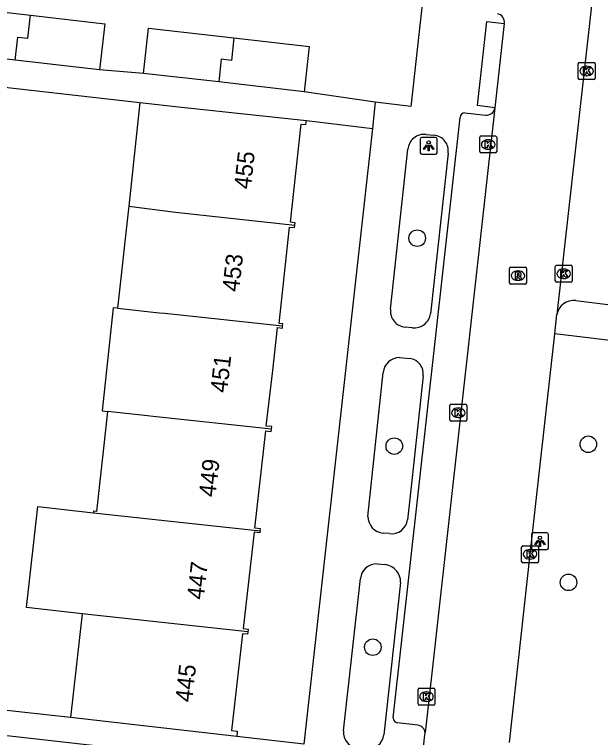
# Model space of a CAD drawing. Extents: x 161928 to 163055, y 386475 to 387428.
# Drawn here: x 162068.43 to 162103.08, y 386978.31 to 387021.04 of the extents above; entities that cross this region are included whole.
import ezdxf

# ---------------------------------------------------------------- set-up
doc = ezdxf.new("R2010")
doc.units = 0
for name, color, linetype in [('IMGEO_Boom', 7, 'Continuous'), ('IMGEO_Kolk', 7, 'Continuous'), ('IMGEO_Lichtpunt', 7, 'Continuous'), ('IMGEO_Pand', 7, 'Continuous'), ('IMGEO_Pand_nummerreeks', 7, 'Continuous'), ('IMGEO_Rijbaan_lokaal_open', 7, 'Continuous'), ('IMGEO_Rioolput', 7, 'Continuous'), ('IMGEO_Voetpad_gesloten', 7, 'Continuous'), ('IMGEO_Voetpad_open', 7, 'Continuous')]:
    doc.layers.add(name, color=color, linetype=linetype)

msp = doc.modelspace()

# ---------------------------------------------------------------- linework, layer by layer
at = {"layer": 'IMGEO_Boom'}
for centre in [(162092.243, 387007.82), (162090.886, 386995.528), (162102.36, 386995.64), (162101.189, 386987.475), (162089.615, 386983.644)]:
    msp.add_circle(centre, 0.489, dxfattribs=at)
at = {"layer": 'IMGEO_Kolk'}
for p, q in [((162101.762, 387017.272), (162101.762, 387018.124)), ((162101.837, 387018.198), (162102.689, 387018.198)), ((162102.763, 387018.124), (162102.763, 387017.272)), ((162102.25, 387017.978), (162102.275, 387017.978)), ((162102.689, 387017.198), (162101.837, 387017.198)), ((162102.273, 387017.418), (162102.248, 387017.418)), ((162095.94, 387012.932), (162095.94, 387013.784)), ((162096.015, 387013.858), (162096.867, 387013.858)), ((162096.941, 387013.784), (162096.941, 387012.932)), ((162096.428, 387013.638), (162096.453, 387013.638)), ((162096.451, 387013.078), (162096.426, 387013.078)), ((162096.867, 387012.858), (162096.015, 387012.858)), ((162100.407, 387005.289), (162100.407, 387006.141)), ((162100.482, 387006.215), (162101.334, 387006.215)), ((162101.408, 387006.141), (162101.408, 387005.289)), ((162100.895, 387005.995), (162100.92, 387005.995)), ((162101.334, 387005.215), (162100.482, 387005.215)), ((162100.918, 387005.435), (162100.893, 387005.435)), ((162094.169, 386997.074), (162094.169, 386997.926)), ((162094.244, 386998), (162095.096, 386998)), ((162095.17, 386997.926), (162095.17, 386997.074)), ((162094.657, 386997.78), (162094.682, 386997.78)), ((162094.68, 386997.22), (162094.655, 386997.22)), ((162095.096, 386997), (162094.244, 386997)), ((162098.417, 386988.711), (162098.417, 386989.563)), ((162098.492, 386989.637), (162099.344, 386989.637)), ((162098.905, 386989.417), (162098.93, 386989.417)), ((162099.418, 386989.563), (162099.418, 386988.711)), ((162099.344, 386988.637), (162098.492, 386988.637)), ((162098.928, 386988.857), (162098.903, 386988.857)), ((162092.289, 386980.297), (162092.289, 386981.149)), ((162092.364, 386981.223), (162093.216, 386981.223)), ((162092.777, 386981.003), (162092.802, 386981.003)), ((162093.29, 386981.149), (162093.29, 386980.297)), ((162092.8, 386980.443), (162092.775, 386980.443)), ((162093.216, 386980.223), (162092.364, 386980.223))]:
    msp.add_line(p, q, dxfattribs=at)
for points in [[(162101.762, 387017.272), (162101.762, 387018.124)], [(162101.837, 387018.198), (162102.689, 387018.198)], [(162102.763, 387018.124), (162102.763, 387017.272)], [(162102.083, 387017.898), (162102.206, 387017.898), (162102.206, 387017.747), (162102.336, 387017.898), (162102.5, 387017.898), (162102.354, 387017.747), (162102.507, 387017.498), (162102.355, 387017.498), (162102.27, 387017.662), (162102.206, 387017.595), (162102.206, 387017.498), (162102.083, 387017.498), (162102.083, 387017.898)], [(162102.689, 387017.198), (162101.837, 387017.198)], [(162095.94, 387012.932), (162095.94, 387013.784)], [(162096.015, 387013.858), (162096.867, 387013.858)], [(162096.941, 387013.784), (162096.941, 387012.932)], [(162096.261, 387013.558), (162096.384, 387013.558), (162096.384, 387013.407), (162096.514, 387013.558), (162096.678, 387013.558), (162096.532, 387013.407), (162096.685, 387013.158), (162096.533, 387013.158), (162096.448, 387013.322), (162096.384, 387013.255), (162096.384, 387013.158), (162096.261, 387013.158), (162096.261, 387013.558)], [(162096.867, 387012.858), (162096.015, 387012.858)], [(162100.407, 387005.289), (162100.407, 387006.141)], [(162100.482, 387006.215), (162101.334, 387006.215)], [(162101.408, 387006.141), (162101.408, 387005.289)], [(162100.728, 387005.915), (162100.851, 387005.915), (162100.851, 387005.764), (162100.981, 387005.915), (162101.145, 387005.915), (162100.999, 387005.764), (162101.152, 387005.515), (162101, 387005.515), (162100.915, 387005.679), (162100.851, 387005.612), (162100.851, 387005.515), (162100.728, 387005.515), (162100.728, 387005.915)], [(162101.334, 387005.215), (162100.482, 387005.215)], [(162094.169, 386997.074), (162094.169, 386997.926)], [(162094.244, 386998), (162095.096, 386998)], [(162095.17, 386997.926), (162095.17, 386997.074)], [(162094.49, 386997.7), (162094.613, 386997.7), (162094.613, 386997.549), (162094.743, 386997.7), (162094.907, 386997.7), (162094.761, 386997.549), (162094.914, 386997.3), (162094.762, 386997.3), (162094.677, 386997.464), (162094.613, 386997.397), (162094.613, 386997.3), (162094.49, 386997.3), (162094.49, 386997.7)], [(162095.096, 386997), (162094.244, 386997)], [(162098.417, 386988.711), (162098.417, 386989.563)], [(162098.492, 386989.637), (162099.344, 386989.637)], [(162099.418, 386989.563), (162099.418, 386988.711)], [(162098.738, 386989.337), (162098.861, 386989.337), (162098.861, 386989.186), (162098.991, 386989.337), (162099.155, 386989.337), (162099.009, 386989.186), (162099.162, 386988.937), (162099.01, 386988.937), (162098.925, 386989.101), (162098.861, 386989.034), (162098.861, 386988.937), (162098.738, 386988.937), (162098.738, 386989.337)], [(162099.344, 386988.637), (162098.492, 386988.637)], [(162092.289, 386980.297), (162092.289, 386981.149)], [(162092.364, 386981.223), (162093.216, 386981.223)], [(162092.61, 386980.923), (162092.733, 386980.923), (162092.733, 386980.772), (162092.863, 386980.923), (162093.027, 386980.923), (162092.881, 386980.772), (162093.034, 386980.523), (162092.882, 386980.523), (162092.797, 386980.687), (162092.733, 386980.62), (162092.733, 386980.523), (162092.61, 386980.523), (162092.61, 386980.923)], [(162093.29, 386981.149), (162093.29, 386980.297)], [(162093.216, 386980.223), (162092.364, 386980.223)]]:
    msp.add_lwpolyline(points, dxfattribs=at)
for centre, start, end in [((162101.839, 387018.122), 91.552, 178.448), ((162101.839, 387018.122), 91.552, 178.448), ((162102.687, 387018.122), 1.552, 88.448), ((162102.687, 387018.122), 1.552, 88.448), ((162101.839, 387017.274), 181.552, 268.448), ((162101.839, 387017.274), 181.552, 268.448), ((162102.687, 387017.274), 271.552, 358.448), ((162102.687, 387017.274), 271.552, 358.448), ((162096.017, 387013.782), 91.552, 178.448), ((162096.017, 387013.782), 91.552, 178.448), ((162096.865, 387013.782), 1.552, 88.448), ((162096.865, 387013.782), 1.552, 88.448), ((162096.017, 387012.934), 181.552, 268.448), ((162096.017, 387012.934), 181.552, 268.448), ((162096.865, 387012.934), 271.552, 358.448), ((162096.865, 387012.934), 271.552, 358.448), ((162100.484, 387006.139), 91.552, 178.448), ((162100.484, 387006.139), 91.552, 178.448), ((162101.332, 387006.139), 1.552, 88.448), ((162101.332, 387006.139), 1.552, 88.448), ((162100.484, 387005.291), 181.552, 268.448), ((162100.484, 387005.291), 181.552, 268.448), ((162101.332, 387005.291), 271.552, 358.448), ((162101.332, 387005.291), 271.552, 358.448), ((162094.246, 386997.924), 91.552, 178.448), ((162094.246, 386997.924), 91.552, 178.448), ((162095.094, 386997.924), 1.552, 88.448), ((162095.094, 386997.924), 1.552, 88.448), ((162094.246, 386997.076), 181.552, 268.448), ((162094.246, 386997.076), 181.552, 268.448), ((162095.094, 386997.076), 271.552, 358.448), ((162095.094, 386997.076), 271.552, 358.448), ((162098.494, 386989.561), 91.552, 178.448), ((162098.494, 386989.561), 91.552, 178.448), ((162099.342, 386989.561), 1.552, 88.448), ((162099.342, 386989.561), 1.552, 88.448), ((162098.494, 386988.713), 181.552, 268.448), ((162098.494, 386988.713), 181.552, 268.448), ((162099.342, 386988.713), 271.552, 358.448), ((162099.342, 386988.713), 271.552, 358.448), ((162092.366, 386981.147), 91.552, 178.448), ((162092.366, 386981.147), 91.552, 178.448), ((162093.214, 386981.147), 1.552, 88.448), ((162093.214, 386981.147), 1.552, 88.448), ((162092.366, 386980.299), 181.552, 268.448), ((162092.366, 386980.299), 181.552, 268.448), ((162093.214, 386980.299), 271.552, 358.448), ((162093.214, 386980.299), 271.552, 358.448)]:
    msp.add_arc(centre, 0.0765, start, end, dxfattribs=at)
for centre, major_axis, ratio, start_param, end_param in [((162102.249, 387017.698), (-0.387, 0.002), 0.722429, 4.712389, 7.853982), ((162102.274, 387017.698), (-0.39, 0.002), 0.717154, 1.570796, 4.712389), ((162096.427, 387013.358), (-0.387, 0.002), 0.722429, 4.712389, 7.853982), ((162096.452, 387013.358), (-0.39, 0.002), 0.717154, 1.570796, 4.712389), ((162100.894, 387005.715), (-0.387, 0.002), 0.722429, 4.712389, 7.853982), ((162100.919, 387005.715), (-0.39, 0.002), 0.717154, 1.570796, 4.712389), ((162094.656, 386997.5), (-0.387, 0.002), 0.722429, 4.712389, 7.853982), ((162094.681, 386997.5), (-0.39, 0.002), 0.717154, 1.570796, 4.712389), ((162098.904, 386989.137), (-0.387, 0.002), 0.722429, 4.712389, 7.853982), ((162098.929, 386989.137), (-0.39, 0.002), 0.717154, 1.570796, 4.712389), ((162092.776, 386980.723), (-0.387, 0.002), 0.722429, 4.712389, 7.853982), ((162092.801, 386980.723), (-0.39, 0.002), 0.717154, 1.570796, 4.712389)]:
    msp.add_ellipse(centre, major_axis=major_axis, ratio=ratio, start_param=start_param, end_param=end_param, dxfattribs=at)
at = {"layer": 'IMGEO_Lichtpunt'}
for p, q in [((162093.323, 387013.772), (162092.515, 387013.772)), ((162093.323, 387013.772), (162092.515, 387013.772)), ((162092.421, 387013.677), (162092.421, 387012.87)), ((162092.421, 387013.677), (162092.421, 387012.87)), ((162093.417, 387012.87), (162093.417, 387013.677)), ((162093.417, 387012.87), (162093.417, 387013.677)), ((162092.515, 387012.776), (162093.323, 387012.776)), ((162092.515, 387012.776), (162093.323, 387012.776)), ((162099.002, 386990.312), (162099.002, 386989.505)), ((162099.002, 386990.312), (162099.002, 386989.505)), ((162099.904, 386990.407), (162099.096, 386990.407)), ((162099.904, 386990.407), (162099.096, 386990.407)), ((162099.998, 386989.505), (162099.998, 386990.312)), ((162099.998, 386989.505), (162099.998, 386990.312)), ((162099.096, 386989.411), (162099.904, 386989.411)), ((162099.096, 386989.411), (162099.904, 386989.411))]:
    msp.add_line(p, q, dxfattribs=at)
for points in [[(162092.795, 387013.341), (162092.834, 387013.313), (162092.646, 387013.051), (162092.608, 387013.078), (162092.795, 387013.341)], [(162093.007, 387013.313), (162093.045, 387013.34), (162093.232, 387013.078), (162093.193, 387013.05), (162093.007, 387013.313)], [(162092.897, 387013.293), (162092.944, 387013.293), (162092.944, 387012.971), (162092.897, 387012.971), (162092.897, 387013.293)], [(162099.376, 386989.976), (162099.415, 386989.948), (162099.227, 386989.686), (162099.189, 386989.713), (162099.376, 386989.976)], [(162099.478, 386989.928), (162099.525, 386989.928), (162099.525, 386989.606), (162099.478, 386989.606), (162099.478, 386989.928)], [(162099.588, 386989.948), (162099.626, 386989.975), (162099.813, 386989.713), (162099.774, 386989.685), (162099.588, 386989.948)]]:
    msp.add_lwpolyline(points, dxfattribs=at)
for centre in [(162092.92, 387013.475), (162099.501, 386990.11)]:
    msp.add_circle(centre, 0.0994, dxfattribs=at)
for centre, start, end in [((162092.515, 387013.677), 90, 180), ((162092.515, 387013.677), 90, 180), ((162093.323, 387013.677), 0, 90), ((162093.323, 387013.677), 0, 90), ((162092.515, 387012.87), 180, 270), ((162092.515, 387012.87), 180, 270), ((162093.323, 387012.87), 270, 0), ((162093.323, 387012.87), 270, 360), ((162099.096, 386990.312), 90, 180), ((162099.096, 386990.312), 90, 180), ((162099.904, 386990.312), 0, 90), ((162099.904, 386990.312), 0, 90), ((162099.096, 386989.505), 180, 270), ((162099.096, 386989.505), 180, 270), ((162099.904, 386989.505), 270, 0), ((162099.904, 386989.505), 270, 360)]:
    msp.add_arc(centre, 0.0946, start, end, dxfattribs=at)
at = {"layer": 'IMGEO_Pand'}
for points in [[(162064.056, 387018.849), (162064.371, 387021.579), (162069.373, 387021.003)], [(162068.461, 387018.341), (162068.619, 387019.707), (162069.216, 387019.638), (162069.373, 387021.003)], [(162069.373, 387021.003), (162073.778, 387020.496), (162073.463, 387017.765)], [(162076.053, 387017.561), (162076.359, 387020.238), (162081.406, 387019.661)], [(162081.406, 387019.661), (162081.253, 387018.321), (162080.656, 387018.389), (162080.503, 387017.052)], [(162081.406, 387019.661), (162085.855, 387019.152), (162085.549, 387016.475)], [(162068.461, 387018.341), (162064.056, 387018.849)], [(162073.463, 387017.765), (162068.461, 387018.341)], [(162080.503, 387017.052), (162076.053, 387017.561)], [(162085.549, 387016.475), (162080.503, 387017.052)], [(162075.844, 387015.83), (162075.182, 387009.711)], [(162075.844, 387015.83), (162078.298, 387015.564), (162080.716, 387015.302), (162085.686, 387014.764)], [(162085.001, 387008.588), (162085.016, 387008.73), (162084.748, 387008.759), (162085.376, 387014.56), (162085.661, 387014.53), (162085.686, 387014.764)], [(162075.182, 387009.711), (162075.164, 387009.548), (162074.529, 387003.678)], [(162075.182, 387009.711), (162077.942, 387009.348), (162085.001, 387008.588)], [(162084.283, 387002.63), (162084.291, 387002.759), (162084.079, 387002.773), (162084.696, 387008.477), (162084.986, 387008.446), (162085.001, 387008.588)], [(162074.529, 387003.678), (162074.26, 387003.707), (162073.604, 386997.613), (162073.925, 386997.579)], [(162074.529, 387003.678), (162076.989, 387003.414), (162077.313, 387003.379), (162084.283, 387002.63)], [(162083.629, 386996.535), (162083.645, 386996.679), (162083.308, 386996.699), (162083.704, 387000), (162083.978, 387002.53), (162084.275, 387002.498), (162084.283, 387002.63)], [(162073.925, 386997.579), (162073.904, 386997.384), (162073.284, 386991.659), (162073.108, 386991.679), (162073.098, 386991.587)], [(162083.629, 386996.535), (162076.631, 386997.288), (162076.287, 386997.325), (162073.925, 386997.579)], [(162082.955, 386990.525), (162082.969, 386990.649), (162082.647, 386990.685), (162083.294, 386996.424), (162083.612, 386996.388), (162083.629, 386996.535)], [(162072.424, 386985.617), (162069.132, 386985.988), (162069.805, 386991.958), (162073.098, 386991.587)], [(162073.098, 386991.587), (162082.955, 386990.525)], [(162082.955, 386990.525), (162082.941, 386990.399), (162082.597, 386990.438), (162081.956, 386984.75), (162082.248, 386984.717), (162082.23, 386984.562)], [(162072.424, 386985.617), (162071.731, 386979.481)], [(162082.23, 386984.562), (162072.424, 386985.617)], [(162082.23, 386984.562), (162082.213, 386984.409), (162081.913, 386984.443), (162081.268, 386978.726), (162081.605, 386978.688), (162081.569, 386978.371)], [(162081.569, 386978.371), (162071.731, 386979.481)]]:
    msp.add_lwpolyline(points, dxfattribs=at)
at = {"layer": 'IMGEO_Rijbaan_lokaal_open'}
for points in [[(162103.766, 387032.467), (162100.497, 387003.3)], [(162097.391, 387020.515), (162096.836, 387015.514)], [(162096.836, 387015.514), (162092.709, 386978.579)], [(162100.379, 387002.167), (162100.497, 387003.3)], [(162097.69, 386978.022), (162098.918, 386989.137), (162100.379, 387002.167)], [(162063.064, 386978.976), (162064.316, 386978.849), (162082.773, 386976.758), (162084.434, 386976.577)], [(162092.553, 386977.189), (162092.697, 386978.472), (162092.709, 386978.579)]]:
    msp.add_lwpolyline(points, dxfattribs=at)
msp.add_arc((162096.908, 387020.594), 0.489, 350.7097, 81.5505, dxfattribs=at)
at = {"layer": 'IMGEO_Rioolput'}
for p, q in [((162097.773, 387006.102), (162098.625, 387006.102)), ((162097.698, 387005.176), (162097.698, 387006.028)), ((162098.186, 387005.882), (162098.211, 387005.882)), ((162098.699, 387006.028), (162098.699, 387005.176)), ((162098.209, 387005.322), (162098.184, 387005.322)), ((162098.625, 387005.102), (162097.773, 387005.102))]:
    msp.add_line(p, q, dxfattribs=at)
for points in [[(162097.773, 387006.102), (162098.625, 387006.102)], [(162097.698, 387005.176), (162097.698, 387006.028)], [(162098.287, 387005.8), (162098.035, 387005.802), (162098.035, 387005.402)], [(162098.213, 387005.721), (162098.159, 387005.721), (162098.159, 387005.64)], [(162098.159, 387005.64), (162098.211, 387005.64)], [(162098.699, 387006.028), (162098.699, 387005.176)], [(162098.035, 387005.402), (162098.159, 387005.402), (162098.159, 387005.564), (162098.17, 387005.564)], [(162098.217, 387005.535), (162098.288, 387005.402), (162098.428, 387005.402), (162098.363, 387005.528)], [(162098.625, 387005.102), (162097.773, 387005.102)]]:
    msp.add_lwpolyline(points, dxfattribs=at)
for centre, radius, start, end in [((162097.775, 387006.026), 0.0765, 91.552, 178.448), ((162097.775, 387006.026), 0.0765, 91.552, 178.448), ((162098.623, 387006.026), 0.0765, 1.552, 88.448), ((162098.623, 387006.026), 0.0765, 1.552, 88.448), ((162098.195, 387005.829), 0.19, 274.7715, 282.9687), ((162098.219, 387005.625), 0.0964, 77.0061, 93.1865), ((162098.233, 387005.682), 0.0378, 276.6634, 79.6772), ((162098.286, 387005.69), 0.109, 350.3612, 89.416), ((162098.284, 387005.69), 0.112, 277.5842, 350.9817), ((162098.169, 387005.511), 0.0533, 26.0293, 88.6989), ((162098.268, 387005.475), 0.108, 29.5134, 73.7905), ((162097.775, 387005.178), 0.0765, 181.552, 268.448), ((162097.775, 387005.178), 0.0765, 181.552, 268.448), ((162098.623, 387005.178), 0.0765, 271.552, 358.448), ((162098.623, 387005.178), 0.0765, 271.552, 358.448)]:
    msp.add_arc(centre, radius, start, end, dxfattribs=at)
for centre, major_axis, ratio, start_param, end_param in [((162098.185, 387005.602), (-0.387, 0.002), 0.722429, 4.712389, 7.853982), ((162098.21, 387005.602), (-0.39, 0.002), 0.717154, 1.570796, 4.712389)]:
    msp.add_ellipse(centre, major_axis=major_axis, ratio=ratio, start_param=start_param, end_param=end_param, dxfattribs=at)
at = {"layer": 'IMGEO_Voetpad_gesloten'}
msp.add_lwpolyline([(162096.836, 387015.514), (162095.799, 387015.661), (162096.356, 387020.626), (162097.391, 387020.515)], dxfattribs=at)
at = {"layer": 'IMGEO_Voetpad_open'}
for points in [[(162094.369, 387037.059), (162092.97, 387025.536), (162092.186, 387018.428), (162091.89, 387015.75), (162091.874, 387015.603), (162089.765, 387015.862)], [(162076.053, 387017.561), (162073.463, 387017.765)], [(162065.663, 387015.752), (162065.756, 387016.989), (162075.844, 387015.83)], [(162089.765, 387015.862), (162085.549, 387016.475)], [(162089.765, 387015.862), (162089.592, 387014.308)], [(162095.067, 387015.22), (162096.271, 387015.08)], [(162085.686, 387014.764), (162089.592, 387014.308)], [(162090.826, 386979.463), (162094.775, 387014.957)], [(162089.592, 387014.308), (162087.995, 387000), (162085.531, 386977.917)], [(162092.767, 387013.947), (162093.227, 387013.899)], [(162090.662, 387003.626), (162091.695, 387013.074)], [(162094.068, 387012.84), (162093.021, 387003.353)], [(162101.617, 387004.128), (162106.81, 387003.494)], [(162091.952, 387002.528), (162091.528, 387002.565)], [(162107.581, 387001.289), (162100.379, 387002.167)], [(162091.202, 387000.759), (162091.814, 387000.704)], [(162089.321, 386991.377), (162090.225, 386999.882)], [(162092.6, 386999.678), (162091.857, 386992.938), (162091.663, 386991.175)], [(162090.611, 386990.355), (162090.231, 386990.39)], [(162089.883, 386988.573), (162090.376, 386988.524)], [(162087.874, 386978.704), (162088.888, 386987.699)], [(162091.257, 386987.471), (162090.259, 386978.472)], [(162071.731, 386979.481), (162064.53, 386980.285)], [(162092.279, 386979.03), (162091.082, 386979.17)], [(162085.531, 386977.917), (162081.569, 386978.371)]]:
    msp.add_lwpolyline(points, dxfattribs=at)
for centre, radius, start, end in [((162096.31, 387015.614), 0.535, 265.8193, 349.2394), ((162095.056, 387014.938), 0.282, 87.8216, 176.1962), ((162092.651, 387012.994), 0.96, 83.0804, 175.236), ((162093.166, 387012.987), 0.914, 350.7532, 86.1561), ((162101.496, 387003.12), 1.015, 83.1546, 169.7954), ((162091.611, 387003.517), 0.956, 173.4468, 264.9966), ((162092.078, 387003.47), 0.95, 262.3965, 352.9217), ((162091.201, 386999.778), 0.981, 89.9245, 173.9007), ((162091.675, 386999.783), 0.931, 353.4962, 81.414), ((162090.327, 386991.391), 1.006, 180.8034, 264.5478), ((162090.727, 386991.291), 0.943, 262.9525, 352.918), ((162089.853, 386987.604), 0.969, 88.209, 174.3826), ((162090.225, 386987.502), 1.033, 358.2632, 81.5723), ((162091.141, 386979.48), 0.316, 183.1222, 259.1665), ((162088.833, 386978.622), 0.962, 175.088, 264.9441), ((162092.25, 386978.572), 0.459, 0.8457, 86.4233), ((162089.293, 386978.572), 0.972, 265.7138, 354.1031)]:
    msp.add_arc(centre, radius, start, end, dxfattribs=at)

# ---------------------------------------------------------------- texts
at = {"layer": 'IMGEO_Pand_nummerreeks'}
for s, rotation, p in [('455', 83.4628, (162082.394, 387010.68)), ('453', 83.4628, (162081.699, 387004.616)), ('451', 83.4456, (162080.996, 386998.646)), ('449', 83.4628, (162080.309, 386992.487)), ('447', 83.4628, (162079.613, 386986.423)), ('445', 83.4602, (162078.918, 386980.359))]:
    msp.add_text(s, height=1, rotation=rotation, dxfattribs=at).set_placement(p)

doc.saveas('drawing.dxf')
